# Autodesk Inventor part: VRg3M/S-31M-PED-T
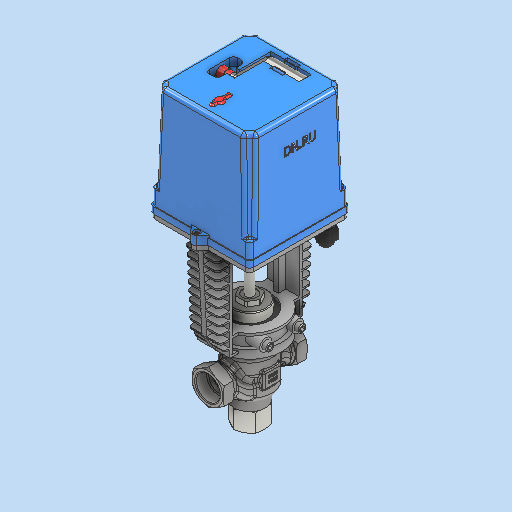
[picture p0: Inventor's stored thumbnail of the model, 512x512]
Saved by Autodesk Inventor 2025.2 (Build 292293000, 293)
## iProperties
Company: DN.RU
Created: 2026-04
Part Number: VRg3M/S-31M-PED-T
Material: Типовые
Document SubType Name: Modeling
Designer: DN.RU
Density: 1.35837 g/cm^3
Appearance: По умолчанию
Description: D230-11265
Mass: 3400 g
Surface Area: 2173.26 cm^2
Volume: 2502.99 cm^3
Author: DN.RU
Title: Клапан регулирующий трехходовой Ду25 Ру25
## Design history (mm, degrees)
derived "Сборка.iam"
node "Твердое тело1"
node "Деталь 1.ipt:1"
node "Деталь 2.ipt:1"
node "Деталь 3.ipt:1"
node "AS 1420 - метрическая M5 x 10:1"
node "AS 1420 - метрическая M5 x 10:2"
node "AS 1427 H - метрическая M3 x 8:1"
node "AS 1427 H - метрическая M3 x 8:2"
node "AS 1421 засверленный конец - метрическая M10 x 12 засверленн"
node "AS 1421 засверленный конец - метрическая M10 x 12 засверленн"
